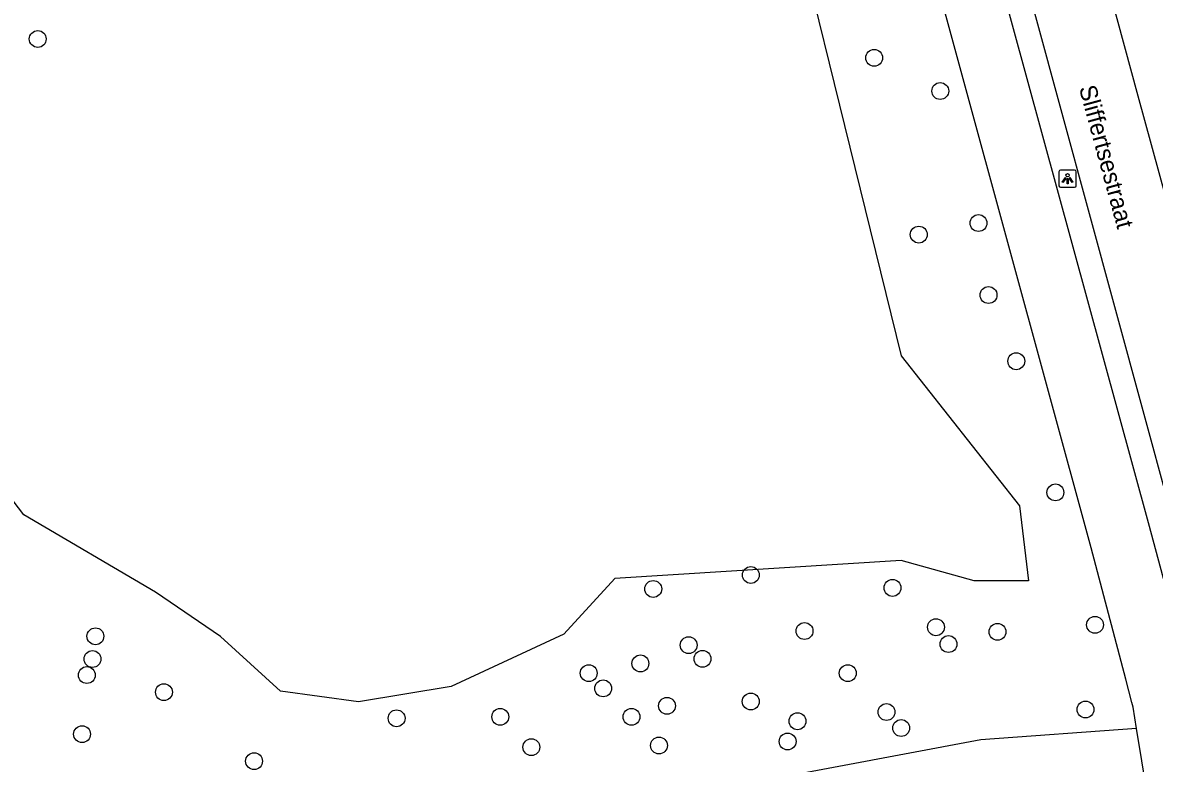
# Model space of a CAD drawing. Extents: x 156664 to 157568, y 383571 to 384421.
# Drawn here: x 157076.5 to 157142.1, y 383832.6 to 383875.5 of the extents above; entities that cross this region are included whole.
import ezdxf

# ---------------------------------------------------------------- set-up
doc = ezdxf.new("R2010")
doc.units = 0
for name, color, linetype in [('IMGEO_Boom', 7, 'Continuous'), ('IMGEO_Fietspad_gesloten', 7, 'Continuous'), ('IMGEO_Lichtpunt', 7, 'Continuous'), ('IMGEO_Loofbos', 7, 'Continuous'), ('IMGEO_Openbare_ruimte_label', 7, 'Continuous'), ('IMGEO_Rijbaan_lokaal_open', 7, 'Continuous')]:
    doc.layers.add(name, color=color, linetype=linetype)

msp = doc.modelspace()

# ---------------------------------------------------------------- linework, layer by layer
at = {"layer": 'IMGEO_Boom'}
for centre in [(157077.331, 383874.599), (157125.875, 383873.506), (157129.713, 383871.581), (157131.932, 383863.92), (157128.464, 383863.249), (157132.516, 383859.743), (157134.124, 383855.902), (157136.395, 383848.292), (157118.722, 383843.499), (157113.054, 383842.689), (157126.937, 383842.75), (157138.694, 383840.608), (157080.678, 383839.943), (157121.837, 383840.249), (157129.463, 383840.468), (157133.033, 383840.201), (157115.11, 383839.428), (157130.188, 383839.492), (157080.51, 383838.624), (157115.911, 383838.639), (157112.309, 383838.369), (157080.178, 383837.693), (157109.31, 383837.804), (157124.343, 383837.806), (157084.655, 383836.701), (157110.149, 383836.921), (157118.713, 383836.162), (157113.852, 383835.905), (157126.593, 383835.549), (157138.144, 383835.692), (157098.159, 383835.184), (157104.175, 383835.273), (157111.793, 383835.272), (157121.426, 383835.014), (157079.903, 383834.264), (157127.442, 383834.621), (157105.98, 383833.51), (157113.386, 383833.61), (157120.853, 383833.835), (157089.886, 383832.699)]:
    msp.add_circle(centre, 0.489, dxfattribs=at)
at = {"layer": 'IMGEO_Fietspad_gesloten'}
for points in [[(157141.11, 383834.602), (157140.909, 383835.831), (157140.837, 383836.103), (157140.48, 383837.452), (157138.465, 383845.068), (157121.363, 383907.733)], [(157145.881, 383828.34), (157144.437, 383836.755), (157141.79, 383846.532), (157125.103, 383907.619)], [(157142.354, 383826.982), (157141.11, 383834.602)]]:
    msp.add_lwpolyline(points, dxfattribs=at)
at = {"layer": 'IMGEO_Lichtpunt'}
for p, q in [((157136.603, 383866.896), (157136.603, 383866.089)), ((157136.603, 383866.896), (157136.603, 383866.089)), ((157137.505, 383866.991), (157136.697, 383866.991)), ((157137.505, 383866.991), (157136.697, 383866.991)), ((157137.599, 383866.089), (157137.599, 383866.896)), ((157137.599, 383866.089), (157137.599, 383866.896)), ((157136.697, 383865.995), (157137.505, 383865.995)), ((157136.697, 383865.995), (157137.505, 383865.995))]:
    msp.add_line(p, q, dxfattribs=at)
for points in [[(157136.977, 383866.56), (157137.016, 383866.532), (157136.828, 383866.27), (157136.79, 383866.297), (157136.977, 383866.56)], [(157137.079, 383866.512), (157137.126, 383866.512), (157137.126, 383866.19), (157137.079, 383866.19), (157137.079, 383866.512)], [(157137.189, 383866.532), (157137.227, 383866.559), (157137.414, 383866.297), (157137.375, 383866.269), (157137.189, 383866.532)]]:
    msp.add_lwpolyline(points, dxfattribs=at)
msp.add_circle((157137.102, 383866.694), 0.0994, dxfattribs=at)
for centre, start, end in [((157136.697, 383866.896), 90, 180), ((157136.697, 383866.896), 90, 180), ((157137.505, 383866.896), 0, 90), ((157137.505, 383866.896), 0, 90), ((157136.697, 383866.089), 180, 270), ((157136.697, 383866.089), 180, 270), ((157137.505, 383866.089), 270, 0), ((157137.505, 383866.089), 270, 360)]:
    msp.add_arc(centre, 0.0946, start, end, dxfattribs=at)
at = {"layer": 'IMGEO_Loofbos'}
for points in [[(157105.291, 383927.602), (157105.217, 383922.59), (157106.471, 383917.709), (157108.582, 383914.146), (157111.616, 383909.66), (157115.706, 383903.591), (157118.477, 383892.64), (157127.449, 383856.225), (157134.31, 383847.517), (157134.838, 383843.163), (157131.671, 383843.163), (157127.449, 383844.35), (157110.825, 383843.295), (157107.856, 383840.062), (157101.325, 383837.028), (157095.948, 383836.137), (157091.43, 383836.764), (157087.933, 383839.93), (157084.173, 383842.503), (157076.52, 383846.989), (157071.375, 383853.718), (157065.965, 383853.982), (157057.767, 383858.53)], [(157141.11, 383834.602), (157132.067, 383833.927), (157119.401, 383831.552), (157103.304, 383826.011), (157098.818, 383826.275), (157097.235, 383822.976), (157098.554, 383816.775), (157100.533, 383804.768), (157104.049, 383785.763)]]:
    msp.add_lwpolyline(points, dxfattribs=at)
at = {"layer": 'IMGEO_Rijbaan_lokaal_open'}
for points in [[(157129.083, 383915.456), (157137.15, 383886.135), (157141.176, 383871.297), (157148.817, 383843.411)], [(157151.838, 383815.069), (157149.3, 383824.346), (157125.795, 383910.624), (157125.737, 383910.814)]]:
    msp.add_lwpolyline(points, dxfattribs=at)

# ---------------------------------------------------------------- texts
at = {"layer": 'IMGEO_Openbare_ruimte_label'}
msp.add_text('Sliffertsestraat', height=1, rotation=285.24507, dxfattribs=at).set_placement((157137.755, 383871.768))

doc.saveas('drawing.dxf')
